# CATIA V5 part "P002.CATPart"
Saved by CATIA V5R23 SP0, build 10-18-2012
Part number: P002
Definition: Flasque avant
Bounding box of the stored display mesh (mm): x -48 to -28, y -90 to 400, z -90 to 258
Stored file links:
  C:\wamp\www\COURS\CONCEPTION GMP1\TITRE 02-SEMESTRE 2\03-TP7-PRESSE MECANIQUE\eleve\P002.CATPart
  C:\Program Files\Dassault Systemes\B11\intel_a\reffiles\standard\MetricThickPitch.txt
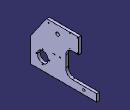
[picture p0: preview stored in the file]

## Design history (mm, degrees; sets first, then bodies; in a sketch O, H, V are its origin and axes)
Set1
  Plane1: type Offset, RefPlane face of Pad1, Offset 28, reversed
  DatumSurface1
Body1 (main body)
  Sketch1 on yz-plane, origin (0, 0, 0), H (0, 1, 0), V (0, 0, 1)
    line L1 (-90, -90) -> (-90, 90)
    line L2 (-90, 90) -> (27.6349, 258)
    line L3 (27.6349, 258) -> (266, 258)
    line L4 (266, 258) -> (266, 146)
    line L5 (266, 146) -> (220, 146)
    line L6 (170, 96) -> (170, 14)
    line L7 (220, -36) -> (400, -36)
    line L8 (400, -36) -> (400, -90)
    line L9 (400, -90) -> (-90, -90)
    circle A1 centre (110, 200) radius 12.5
    point P8 (110, 200)
    circle A2 centre (0, 0) radius 40
    arc A3 centre (220, 96) radius 50 from (220, 146) to (170, 96) ccw
    arc A4 centre (220, 14) radius 50 from (170, 14) to (220, -36) ccw
    reference intersected line E1 through (0, 0) direction (0, 1) from zx-plane
    reference intersected line E2 through (0, 0) direction (0, 1) from zx-plane
    reference intersected line E3 through (0, 0) direction (0, 1) from zx-plane
    distance L9 H = 90
    length L8 = 54
    length L4 = 112
    radius A1 = 12.5
    radius A2 = 40
    radius A3 = 50
    radius A4 = 50 {= Sketch1.radius(A3)}
    distance E1 L6 = 170
    distance E2 L1 = 90
    angle L2 L1 = 145
    length L1 = 180
    distance E3 L8 = 400
    distance P8 L4 = 156
    distance P8 L3 = 58
    distance L4 L1 = 356
    distance L3 L9 = 348
    vertical: L1 V, L4 V, L6 V, L8 V
    horizontal: L3 H, L5 H, L7 H, L9 H
    tangency: A3 L5, A3 L6, A4 L6, A4 L7
  Pad1: profile Sketch1, direction (-1, 0, 0), length 48, opposite side length -28
  Sketch2 on face of Pad1, origin (-28, -11.1167, 64.1401), H (0, 1, 0), V (0, 0, 1)
    point P1 (11.1167, -16.1401)
    reference intersected line E1 through (11.1167, 0) direction (0, 1) from zx-plane
    reference projected point E2 (11.1167, -64.1401) from axis of face of Pad1
    distance P1 E2 = 48
    coincidence: P1 E1
  Hole1: placed by Sketch2, at (-28, 0, 48) direction (-1, 0, 0), diameter 6.647, through (limit type 3), threaded "M8", thread diameter 8, thread depth 10, pitch 1.25
  CircPattern1: of Hole1, instances 4, angular step 90, axis from face of Pad1
  Sketch3 on face of Pad1, origin (-48, 23.108, 153.5042), H (0, 1, 0), V (0, 0, -1)
    point P1 (20.892, -84.4958)
    reference projected line E1 (242.892, 7.5042) -> (242.892, -104.4958) from edge [face of Pad1 | face of Pad1]
    reference projected line E2 (242.892, -104.4958) -> (4.5268, -104.4958) from edge [face of Pad1 | face of Pad1]
    distance P1 E1 = 222
    distance P1 E2 = 20
  Hole2: placed by Sketch3, at (-48, 44, 238) direction (1, 0, 0), diameter 6.647, through (limit type 3), threaded "M8", thread diameter 8, thread depth 10, pitch 1.25
  Sketch4 on face of Pad1, origin (-48, 121.4514, 6.5813), H (0, 1, 0), V (0, 0, -1)
    point P1 (6.5486, -53.4187)
    reference projected line E1 (-211.4514, -83.4187) -> (-211.4514, 96.5813) from edge [face of Pad1 | face of Pad1]
    reference projected line E2 (-211.4514, 96.5813) -> (278.5486, 96.5813) from edge [face of Pad1 | face of Pad1]
    distance P1 E1 = 218
    distance P1 E2 = 150
  Hole3: placed by Sketch4, at (-48, 128, 60) direction (1, 0, 0), diameter 8, through (limit type 3)
  Sketch5 on face of Pad1, origin (-28, 136.9862, 5.2935), H (0, 1, 0), V (0, 0, 1)
    point P1 (-46.9862, 54.7065)
    reference projected line E1 (33.0138, 8.7065) -> (33.0138, 90.7065) from edge [face of Pad1 | face of Pad1]
    reference projected line E2 (-226.9862, -95.2935) -> (263.0138, -95.2935) from edge [face of Pad1 | face of Pad1]
    distance P1 E1 = 80
    distance P1 E2 = 150
  Hole4: placed by Sketch5, at (-28, 90, 60) direction (-1, 0, 0), diameter 4.917, through (limit type 3), threaded "M6", thread diameter 6, thread depth 10, pitch 1
  RectPattern1: of Hole4, direction 1 instances 2, spacing 14, along face of Pad1 reversed
  Sketch6 on face of Pad1, origin (-28, 241.4804, 205.9329), H (0, 1, 0), V (0, 0, 1)
    point P1 (16.5196, 46.0671)
    reference projected line E1 (24.5196, -59.9329) -> (24.5196, 52.0671) from edge [face of Pad1 | face of Pad1]
    reference projected line E2 (24.5196, 52.0671) -> (-213.8455, 52.0671) from edge [face of Pad1 | face of Pad1]
    distance P1 E1 = 8
    distance P1 E2 = 6
  Hole5: placed by Sketch6, at (-28, 258, 252) direction (-1, 0, 0), diameter 6, through (limit type 3)
  RectPattern2: of Hole5, direction 1 instances 2, spacing 58, along face of Pad1 reversed, direction 2 instances 2, spacing 100, along face of Pad1 reversed
  Sketch7 on face of Pad1, origin (-28, 328.6362, -64.747), H (0, 1, 0), V (0, 0, 1)
    point P1 (-24.6362, 4.747)
    reference intersected line E1 (71.3638, 28.747) -> (71.3638, -25.253) from face of Pad1
    reference intersected line E2 (71.3638, -25.253) -> (-418.6362, -25.253) from face of Pad1
    distance P1 E1 = 96
    distance P1 E2 = 30
  Hole6: placed by Sketch7, at (-28, 304, -60) direction (-1, 0, 0), diameter 16, through (limit type 3)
